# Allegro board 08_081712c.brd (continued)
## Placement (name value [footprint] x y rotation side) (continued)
R474  33  [R0603]  205.49 25.97 90 top
R475  1K  [R0402]  205.61 15.81 90 top
R476  10  [R0402]  198.63 17.97 180 top
R477  150  [R0402]  190.75 18.86 0 top
R478  10  [R0402]  198.63 19.75 180 top
R479  5.1K  [R0402]  206.12 12.13 180 top
R480  5.1K  [R0402]  210.69 10.86 180 bottom
R481  30.1K  [R0201]  205.49 10.86 180 bottom
R482  47K  [R0201]  203.71 10.86 180 bottom
R483  18.2K  [R0402]  224.03 14.16 0 top
R484  10K  [R0201]  190.88 29.53 90 top
R485  10K  [R0201]  196.21 30.04 90 top
R486  100K  [R0402]  218.19 12.26 0 top
R487  330  [R0402]  197.61 30.42 90 top
R488  1K  [R0402]  195.71 62.8 270 top
R489  3K  [R0402]  213.49 48.83 270 top
R490  49.9K  [R0402]  198.25 48.83 90 top
R491  100K  [R0402]  197.1 48.83 270 top
R492  33  [R0603]  212.85 38.42 90 top
R493  33  [R0603]  215.9 38.42 90 top
R494  33  [R0603]  214.38 38.42 90 top
R495  33  [R0603]  217.42 38.42 90 top
R496  10K  [R0201]  211.45 37.78 90 top
R497  0  [R0201]  229.49 19.75 270 top
R498  0  [R0201]  229.49 23.56 90 top
R499  33  [R0603]  191.77 33.85 90 bottom
R500  33  [R0603]  190.25 33.85 90 bottom
R501  33  [R0603]  193.29 33.85 90 bottom
R502  33  [R0402]  180.96 127.13 270 top
R503  33  [R0402]  179.69 127.13 270 top
R504  20K  [R0402]  25.27 115.51 180 bottom
R505  20K  [R0402]  25.27 114.36 180 bottom
R506  20K  [R0402]  25.27 113.22 180 bottom
R507  20K  [R0402]  25.27 112.08 180 bottom
R508  20K  [R0402]  25.27 110.93 180 bottom
R509  10K  [R0402]  25.27 115.51 180 top
R510  10K  [R0402]  25.27 114.36 180 top
R511  10K  [R0402]  25.27 113.22 180 top
R512  10K  [R0402]  25.27 112.08 180 top
R513  10K  [R0402]  25.27 110.93 180 top
R514  10K  [R0402]  70.74 81.28 90 top
R515  0  [R0402]  71.88 81.28 270 top
R516  2.94K  [R0402]  64.39 91.06 90 top
R517  10K  [R0402]  386.08 81.28 90 top
R518  0  [R0402]  387.22 81.28 270 top
R519  2.94K  [R0402]  379.73 91.06 90 top
R520  0  [R0402]  130.05 89.6 0 bottom
R521  0  [R0402]  130.05 91.12 0 bottom
R522  10K  [R0402]  240.28 90.04 0 top
R523  10K  [R0402]  203.2 71.95 0 top
R524  10K  [R0402]  137.41 88.58 0 bottom
R525  10K  [R0402]  264.41 88.58 0 bottom
R526  0  [R0402]  257.05 89.6 180 bottom
R527  0  [R0402]  257.05 91.12 180 bottom
R528  10K  [R0402]  203.2 70.8 180 top
R529  3K  [R0402]  279.65 78.55 90 bottom
R530  3K  [R0402]  277.62 78.55 90 bottom
R531  0  [R0402]  207.26 70.8 0 top
R532  0  [R0402]  202.18 63.69 0 top
R533  10K  [R0402]  10.41 32.64 180 bottom
R534  10K  [R0402]  378.08 32.64 180 bottom
R535  10K  [R0402]  86.23 39.5 0 top
R536  10K  [R0402]  88.77 39.5 0 top
R537  10K  [R0402]  88.77 37.97 180 top
R538  10K  [R0402]  86.23 37.97 180 top
R539  10K  [R0402]  72.14 39.5 0 top
R540  10K  [R0402]  74.68 39.5 0 top
R541  10K  [R0402]  74.68 37.97 180 top
R542  10K  [R0402]  72.14 37.97 180 top
R543  10K  [R0402]  349.15 39.47 0 top
R544  10K  [R0402]  351.69 39.47 0 top
R545  10K  [R0402]  351.69 37.95 180 top
R546  10K  [R0201]  243.71 27.05 0 bottom
R547  10K  [R0201]  246.51 24.89 180 bottom
R548  10K  [R0201]  241.05 24.24 0 bottom
R549  0  [R0402]  238.73 28.37 180 top
R550  0  [R0402]  233.15 28.75 180 top
R551  10K  [R0201]  233.15 26.47 0 top
R552  330  [R0402]  225.73 28.45 0 top
R553  10K  [R0402]  349.15 37.95 180 top
R554  10K  [R0402]  335.05 39.47 0 top
R555  10K  [R0402]  337.59 39.47 0 top
R556  10K  [R0402]  337.59 37.95 180 top
R557  10K  [R0402]  335.05 37.95 180 top
R558  3K  [R0402]  277.29 73.09 90 bottom
R559  3K  [R0402]  278.43 73.09 90 bottom
R560  3K  [R0402]  279.58 73.09 90 bottom
R561  3K  [R0402]  280.72 73.09 90 bottom
R562  3K  [R0402]  281.86 73.09 90 bottom
R563  3K  [R0402]  283.01 73.09 90 bottom
R564  10K  [R0603]  39.12 20.37 0 top
R565  75  [R0603]  36.07 20.37 0 top
R566  249  [R0805]  27.3 17.25 270 top
R567  107  [R0402]  26.8 14.91 180 top
R568  15K  [R0603]  400.69 20.37 0 top
R569  10K  [R0603]  406.78 20.37 0 top
R570  75  [R0603]  403.73 20.37 0 top
R571  249  [R0805]  394.97 17.25 270 top
R572  107  [R0402]  394.46 14.91 180 top
R573  33  [R0402]  19.18 26.29 0 top
R574  33  [R0402]  19.18 28.19 0 top
R575  33  [R0402]  9.27 28.96 180 top
R576  33  [R0402]  9.27 26.92 180 top
R577  33  [R0402]  97.92 114.05 90 top
R578  33  [R0402]  386.84 26.29 0 top
R579  33  [R0402]  386.84 28.19 0 top
R580  33  [R0402]  376.94 28.96 180 top
R581  33  [R0402]  376.94 26.92 180 top
R582  33  [R0402]  228.6 108.46 90 top
R583  0  [R0402]  205.77 74.36 270 top
R584  0  [R0402]  204.63 74.36 270 top
R585  0  [R0402]  210.34 82.74 0 top
R586  0  [R0402]  182.37 76.52 90 top
R587  0  [R0402]  309.4 76.52 90 top
R588  3K  [R0402]  152.65 78.55 90 bottom
R589  3K  [R0402]  150.62 78.55 90 bottom
R590  10K  [R0402]  151.26 92.01 180 top
R591  18.2K  [R0402]  105.41 56.77 180 bottom
R592  100K  [R0402]  96.9 58.8 180 bottom
R593  187K  [R0402]  100.84 56.77 0 bottom
R594  1MEG  [R0402_A]  96.39 56.77 90 bottom
R595  18.2K  [R0402]  232.41 56.77 180 bottom
R596  100K  [R0402]  223.9 58.8 180 bottom
R597  187K  [R0402]  227.84 56.77 0 bottom
R598  1MEG  [R0402_A]  223.39 56.77 90 bottom
R599  0  [R0402]  208.53 24.07 90 bottom
R600  60.4  [R0402]  188.85 77.72 90 bottom
R601  60.4  [R0402]  189.99 77.72 90 bottom
R602  60.4  [R0402]  191.13 77.72 90 bottom
R603  60.4  [R0402]  192.28 77.72 90 bottom
S1  JS102011JCQN  [SWSML335W142H220]  221.93 87.06 270 top
S2  JS102011JCQN  [SWSML335W142H220]  228.92 87.19 270 top
S3  JS102011JCQN  [SWSML335W142H220]  330.33 155.19 270 top
S4  JS102011JCQN  [SWSML335W142H220]  311.28 155.19 270 top
S5  JS102011JCQN  [SWSML335W142H220]  290.7 155.19 270 top
S6  JS102011JCQN  [SWSML335W142H220]  271.65 155.19 270 top
S7  JS102011JCQN  [SWSML335W142H220]  252.6 155.19 270 top
S8  JS102011JCQN  [SWSML335W142H220]  233.55 155.19 270 top
S9  JS102011JCQN  [SWSML335W142H220]  212.98 155.19 270 top
S10  JS102011JCQN  [SWSML335W142H220]  193.93 155.19 270 top
S11  MCDM(R)-08-T  [SWSML837W244H153]  204.6 55.82 180 top
S12  SD08H0SBR  [SWSML858W263H160]  72.64 58.17 180 top
S13  SD08H0SBR  [SWSML858W263H160]  330.2 58.17 180 top
S14  ELUMOASAQ6C12  [SWSML1110W450H237]  244.22 10.67 90 bottom
S15  KJ01RTR  [SWSML106W240H140]  146.68 90.23 90 top
S16  SD08H0SBR  [SWSML858W263H160]  170.81 131.45 90 top
SOMA  10151114-001TLF  [CNAMP10151114-001_MXM]  144.14 69.99 0 top
SOMB  10151114-001TLF  [CNAMP10151114-001_MXM]  271.15 69.99 0 top
TP1  TESTPAD  [TPSMC30]  103.39 92.14 270 top
TP2  TESTPAD  [TPSMC30]  99.94 92.14 270 top
TP3  TESTPAD  [TPSMC30]  97.4 83.31 270 top
TP4  TESTPAD  [TPSMC30]  101.09 91.02 270 top
TP5  TESTPAD  [TPSMC30]  97.4 87.88 270 top
TP6  TESTPAD  [TPSMC30]  104.9 79.2 270 top
TP7  TESTPAD  [TPSMC30]  111.38 87.46 270 top
TP8  TESTPAD  [TPSMC30]  102.93 79.98 270 top
TP9  TESTPAD  [TPSMC30]  108.39 90.25 270 top
TP10  TESTPAD  [TPSMC30]  112.53 86.32 270 top
TP11  TESTPAD  [TPSMC30]  107.04 79.98 270 top
TP12  TESTPAD  [TPSMC30]  106.43 91.02 270 top
TP13  TESTPAD  [TPSMC30]  111.38 85.18 270 top
TP14  WHT  [CNLOOPTP]  217.04 67.63 270 top
TP15  WHT  [CNLOOPTP]  221.61 67.63 270 top
TP16  TESTPAD  [TPC65D45]  387.1 114.68 0 top
TP17  TESTPAD  [TPC65D45]  387.1 160.27 0 top
TP18  TESTPAD  [TPC65D45]  406.91 109.73 180 top
TP19  TESTPAD  [TPC65D45]  406.91 155.32 180 top
TP20  TESTPAD  [TPC65D45]  387.1 137.54 0 top
TP21  TESTPAD  [TPC65D45]  387.1 180.72 0 top
TP22  TESTPAD  [TPC65D45]  406.91 132.59 180 top
TP23  BLK  [CNKEY5001TP]  216.92 6.29 0 top
TP24  BLK  [CNKEY5001TP]  226.06 6.29 0 top
TP25  5016  [CNKEY5016TP]  345.57 181.99 180 top
TP26  5016  [CNKEY5016TP]  400.37 180.34 90 top
TP27  5016  [CNKEY5016TP]  400.37 137.16 90 top
TP28  5016  [CNKEY5016TP]  400.37 114.3 90 top
TP29  5016  [CNKEY5016TP]  400.37 159.89 90 top
TP30  TESTPAD  [TPC65D45]  102.36 76.33 180 top
TP31  TESTPAD  [TPC65D45]  229.36 76.33 180 top
U1  ADIN1300CCPZ  [QFN40_6X6_PAD2_8X2_8_A]  136.52 43.44 270 bottom
U2  ADIN1300CCPZ  [QFN40_6X6_PAD2_8X2_8_A]  263.53 43.44 270 bottom
U3  LT8609EMSE#TRPBF  [MSOP10_PAD1_88X1_68]  399.42 130.81 270 top
U4  LT8609EMSE#TRPBF  [MSOP10_PAD1_88X1_68]  399.42 173.99 270 top
U5  SN74LVC2G14DBVR  [SOT23_6]  163.45 27.69 180 bottom
U6  SN74LVC2G14DBVR  [SOT23_6]  290.45 27.69 180 bottom
U7  TC7MBL3126CFT(EL)  [TSSOP14]  219.96 43.81 0 bottom
U8  ADP5587ACPZ-1  [QFN24_4X4_PAD2_1X2_1]  30.48 114.24 180 top
U9  TC7MBL3125CFT(EL)  [TSSOP14]  207.01 87.38 0 top
U10  24AA01T-I/OT  [SOT23-5L]  278.64 81.98 180 bottom
U11  NC7SP14L6X  [UPAK6]  124.27 41.21 180 bottom
U12  NC7SP14L6X  [UPAK6]  251.27 41.21 180 bottom
U13  ADP223ACPZ  [QFN8_2X2_PAD1_6X1]  219.07 78.74 0 bottom
U14  TC7MBL3257CFK(EL)  [VSSOP16]  236.6 96.27 270 top
U15  TC7MBL3257CFK(EL)  [VSSOP16]  236.6 81.66 270 top
U16  LSF0204GU12-Q100X  [UQFN12_2X1_7]  307.85 111.38 0 top
U17  LSF0204GU12-Q100X  [UQFN12_2X1_7]  230.12 111.38 0 top
U18  ADAU1979WBCPZ  [QFN40_6X6_PAD3_9X3_9]  300.99 121.67 270 top
U19  ADAU1979WBCPZ  [QFN40_6X6_PAD3_9X3_9]  223.27 121.67 270 top
U20  LSF0204GU12-Q100X  [UQFN12_2X1_7]  301.5 111.38 0 top
U21  LSF0204GU12-Q100X  [UQFN12_2X1_7]  223.77 111.38 0 top
U22  ADA4841-2YRZ  [SO8]  330.33 147.57 90 top
U23  ADA4841-2YRZ  [SO8]  311.28 147.57 90 top
U24  ADA4841-2YRZ  [SO8]  290.7 147.57 90 top
U25  ADA4841-2YRZ  [SO8]  271.65 147.57 90 top
U26  ADA4841-2YRZ  [SO8]  252.6 147.57 90 top
U27  ADA4841-2YRZ  [SO8]  233.55 147.57 90 top
U28  ADA4841-2YRZ  [SO8]  212.98 147.57 90 top
U29  ADA4841-2YRZ  [SO8]  193.93 147.57 90 top
U30  NXU0104GU12-Q100X  [QFN12_2X1_7]  115.06 103.87 0 top
U31  NXU0104GU12-Q100X  [QFN12_2X1_7]  118.49 103.87 180 bottom
U32  LSF0204GU12-Q100X  [UQFN12_2X1_7]  126.24 103.87 0 top
U33  ADAU1966AWBSTZ  [LQFP80]  108.08 121.67 270 top
U34  TC7MBL3257CFK(EL)  [VSSOP16]  299 102.6 270 bottom
U35  TC7MBL3257CFK(EL)  [VSSOP16]  309.04 102.6 270 bottom
U36  TC7MBL3257CFK(EL)  [VSSOP16]  221.28 102.6 270 bottom
U37  TC7MBL3257CFK(EL)  [VSSOP16]  231.31 102.6 270 bottom
U38  TC7MBL3257CFK(EL)  [VSSOP16]  112.86 96.91 90 bottom
U39  TC7MBL3257CFK(EL)  [VSSOP16]  130.38 96.91 90 bottom
U40  TC7MBL3257CFK(EL)  [VSSOP16]  122.09 96.89 270 bottom
U41  ADM3056EBRIZ  [SO16WB_A]  88.65 31.12 180 top
U42  ADM3056EBRIZ  [SO16WB_A]  74.55 31.12 180 top
U43  ADM3056EBRIZ  [SO16WB_A]  351.56 31.09 180 top
U44  ADM3056EBRIZ  [SO16WB_A]  337.46 31.09 180 top
U45  TC7MBL3257CFK(EL)  [VSSOP16]  125.35 81.72 90 bottom
U46  TC7MBL3257CFK(EL)  [VSSOP16]  141.86 81.72 90 bottom
U47  TC7MBL3257CFK(EL)  [VSSOP16]  252.35 81.72 90 bottom
U48  TC7MBL3257CFK(EL)  [VSSOP16]  268.86 81.72 90 bottom
U49  LT8609EMSE#TRPBF  [MSOP10_PAD1_88X1_68]  399.42 153.54 270 top
U50  LT8609EMSE#TRPBF  [MSOP10_PAD1_88X1_68]  399.42 107.95 270 top
U51  ADP5587ACPZ-1  [QFN24_4X4_PAD2_1X2_1]  258.44 119.32 180 top
U52  TC7MBL3257CFK(EL)  [VSSOP16]  236.6 88.77 270 top
U53  IS25LP032D-JKLE  [WSON8_5X6_PAD4X3_4]  202.44 34.99 270 top
U54  ATSAME70Q21B-CFNT  [BGA144_6X6]  206.65 20.51 90 top
U55  LT8618EDDB-3.3#TRPBF  [DFN10_3X2_PAD2_39X0_64]  221.23 12.26 90 top
U56  ADM6315-29D2ARTZR7  [SOT143A]  193.55 29.4 90 top
U57  ADP151ACBZ-1.8-R7  [WLCSP4H26]  232.03 20.64 0 top
U58  74AVC4T245BQ,115  [DQFN16_3_5X2_5_PAD2_15X1_15]  214.63 34.35 0 top
U59  74AVC2T245GUX  [QFN10_1_8X1_4]  219.96 21.91 0 top
U60  74AVC4T245BQ,115  [DQFN16_3_5X2_5_PAD2_15X1_15]  192.02 37.78 180 bottom
U61  TC7MBL3257CFK(EL)  [VSSOP16]  133.73 89.85 90 bottom
U62  TC7MBL3257CFK(EL)  [VSSOP16]  260.73 89.85 90 bottom
U63  LSF0204GU12-Q100X  [UQFN12_2X1_7]  14.35 22.35 180 top
U64  74LVC1G08GW-Q100  [SOT353]  243.71 24.89 270 bottom
U65  IS72WVO32M8AWO256-200HLA2  [BGA24_8X6]  104.39 85.09 0 bottom
U66  LTC2916HDDB-1#TRMPBF  [DFN8_3X2_PAD2_15X0_56_05-08-1702]  235.94 28.12 90 top
U67  TC7MBL3257CFK(EL)  [VSSOP16]  14.1 31.37 270 bottom
U68  LSF0204GU12-Q100X  [UQFN12_2X1_7]  382.02 22.35 180 top
U69  TC7MBL3257CFK(EL)  [VSSOP16]  381.76 31.37 270 bottom
U70  SN65LVDS2DR  [SO8NB-5]  37.34 25.2 0 top
U71  SN74LVC1G08DBVT  [SOT23-5L-2]  28.19 23.16 180 top
U72  SN65LVDS2DR  [SO8NB-5]  405 25.2 0 top
U73  SN74LVC1G08DBVT  [SOT23-5L-2]  395.86 23.16 180 top
U74  TC7MBL3125CFT(EL)  [TSSOP14]  14.22 26.92 180 top
U75  TC7MBL3125CFT(EL)  [TSSOP14]  381.89 26.92 180 top
U76  24AA01T-I/OT  [SOT23-5L]  151.64 81.98 180 bottom
U77  LT8609EMSE#TRPBF  [MSOP10_PAD1_88X1_68]  102.49 59.31 270 bottom
U78  LT8609EMSE#TRPBF  [MSOP10_PAD1_88X1_68]  229.49 59.31 270 bottom
U79  LSF0204GU12-Q100X  [UQFN12_2X1_7]  190.37 80.9 0 bottom
U80  LSF0204GU12-Q100X  [UQFN12_2X1_7]  190.37 86.36 0 top
U81  NXU0104GU12-Q100X  [QFN12_2X1_7]  180.12 123.22 180 top
Y1  25MEGHZ  [YSML79W63H32]  145.8 38.23 270 bottom
Y2  25MEGHZ  [YSML79W63H32]  272.8 38.23 270 bottom
Y3  24.576MEGHZ  [YSML98W79H35]  183.51 128.35 180 top
Y5  32.768KHZ  [YSML126W59H26]  208.88 26.86 180 top
Y6  12MEGHZ  [YSML126W98H31]  213.99 18.1 45 top

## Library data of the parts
A1 A2 = ADA4610_1_V2: User Part Number: UPN; Tolerance: N/A; alternate symbols: (SOT23-5L); tolerance: N/A
C1-C27 C32-C35 C37 C39-C53 C58-C61 C63 C65-C68 C72-C80 C85-C88 C91-C98 C101 C102 C105-C110 C168-C173 C175 C176 C178 C179 C181 C183 C192 C194-C198 C263-C293 C295 C297 C299 C311 C312 C330 C339 C341 C344 C351 C359 C361-C382 C385-C390 C393 C397 C398 C417 C423 C428-C433 = CAP: User Part Number: UPN; Tolerance: 10; alternate symbols: (C0402); tolerance: 10
C28 C29 C36 C54 C55 C62 = CAP: User Part Number: UPN; Tolerance: 10; alternate symbols: (C0805); tolerance: 10
C30 C31 C38 C56 C57 C64 C117-C120 C131-C134 C145-C148 C159-C162 C188 C190 C191 C193 = CAP: User Part Number: UPN; Tolerance: 10; alternate symbols: (C0603); tolerance: 10
C69-C71 = CAP: Tolerance: 10; User Part Number: UPN; alternate symbols: (C0805H60); tolerance: 10
C81 C82 C89 C90 C99 C100 = CAP: User Part Number: UPN; Tolerance: 10; alternate symbols: (C0805H55); tolerance: 10
C83 C84 C111 C112 C125 C126 C139 C140 C153 C154 C174 C303 C304 C315 C316 C321-C324 C326-C329 C331-C338 C340 C342 C345 C346 C348-C350 C352-C354 C357 C358 C383 C394 C396 C419 C425 = CAP: User Part Number: UPN; Tolerance: 5; alternate symbols: (C0402); tolerance: 5
C103 C104 = CAP: Tolerance: 20; User Part Number: UPN; alternate symbols: (C1210H110); tolerance: 20
C113-C116 C121-C124 C127-C130 C135-C138 C141-C144 C149-C152 C155-C158 C163-C166 = CAPP: Tolerance: 20; User Part Number: UPN; alternate symbols: (CPLSMSQ169H217); tolerance: 20
C167 C177 C180 C182 C184-C187 C189 C294 C296 C309 C310 C384 C391 C392 C416 C422 = CAP: Tolerance: 10; User Part Number: UPN; alternate symbols: (C0805H53); tolerance: 10
C199-C206 C215-C222 C231-C238 C247-C250 C255-C258 C399-C414 = CAP: User Part Number: UPN; Tolerance: 5; alternate symbols: (C0805); tolerance: 5
C207-C214 C223-C230 C239-C246 C251-C254 C259-C262 = CAPP: Tolerance: 10; User Part Number: UPN; alternate symbols: (C2312); tolerance: 10
C298 = CAP: User Part Number: UPN; Tolerance: 5; alternate symbols: (C1206); tolerance: 5
C300 C301 C313 C314 C418 C424 = CAP: Tolerance: 5; User Part Number: UPN; alternate symbols: (C0805-2); tolerance: 5
C302 C415 = CAP: Tolerance: -20%, +80%; User Part Number: UPN; alternate symbols: (C1210); tolerance: -20%, +80%
C305 C306 C317 C318 C420 C426 = CAP: Tolerance: 10; User Part Number: UPN; alternate symbols: (C1210H106); tolerance: 10
C307 C308 C319 C320 C421 C427 = CAP: Tolerance: -20%, +80%; User Part Number: UPN; alternate symbols: (C1206H71-2); tolerance: -20%, +80%
C325 C347 = CAP: Tolerance: 10; User Part Number: UPN; alternate symbols: (C0201); tolerance: 10
C343 C355 C356 = CAP: User Part Number: UPN; Tolerance: 20; alternate symbols: (C0603); tolerance: 20
C360 C395 = CAP: User Part Number: UPN; Tolerance: 20; alternate symbols: (C0402); tolerance: 20
D1-D4 = DIOTVS6P_V2: User Part Number: UPN; Tolerance: N/A; alternate symbols: (SOT23_6); tolerance: N/A
D5-D8 = DIO3P_V5: User Part Number: UPN; Tolerance: N/A; alternate symbols: (SOT23-M3); tolerance: N/A
D9 D10 = DIOSCHOTTKY: User Part Number: UPN; Tolerance: N/A; alternate symbols: (SMC); tolerance: N/A
D11 = DIOZNR: User Part Number: UPN; Tolerance: 5; alternate symbols: (SOD123-2); tolerance: 5
D12 = DIOLED_4P_V32: User Part Number: UPN; Tolerance: N/A; alternate symbols: (LED1210H28); tolerance: N/A
D13 = DIOTVS5P_V4: User Part Number: UPN; Tolerance: N/A; alternate symbols: (SC70-5_A); tolerance: N/A
DS1-DS20 DS24-DS26 = DIOLED: Tolerance: N/A; User Part Number: UPN; alternate symbols: (LED0603); tolerance: N/A
DS21 DS22 = DIOLED: User Part Number: UPN; Tolerance: N/A; alternate symbols: (LED0603H50); tolerance: N/A
DS23 = DIOLED: Tolerance: N/A; User Part Number: UPN; alternate symbols: (LED0805_A); tolerance: N/A
E3-E5 = FERRITE: User Part Number: UPN; Tolerance: 25; alternate symbols: (L0402); tolerance: 25
F1 = FSFUSE: Tolerance: N/A; User Part Number: UPN; alternate symbols: (F2920); tolerance: N/A
J1 J2 = CN3P_V15: User Part Number: UPN; Tolerance: N/A; alternate symbols: (CNSWITCHCRAFTPJRAS1X2SXXXX); tolerance: N/A
J4 J5 P3 P4 = CN100P_V2: Tolerance: N/A; User Part Number: UPN; alternate symbols: (CNSAMTECLSS-150-01-X-DV-A); tolerance: N/A
L1 L5-L7 L9 L10 = IND: Tolerance: 20; User Part Number: UPN; alternate symbols: (LSML208W216H122); tolerance: 20
L2 = IND: User Part Number: UPN; Tolerance: 20; alternate symbols: (LSMSQ157H122); tolerance: 20
L3 L4 = IND: User Part Number: UPN; Tolerance: 5; alternate symbols: (L0402); tolerance: 5
L8 = IND: Tolerance: 20; User Part Number: UPN; alternate symbols: (LSMSQ118H47); tolerance: 20
M1 M2 = MODC6842135TR: User Part Number: UPN; Tolerance: N/A; alternate symbols: (MC6842135TR); tolerance: N/A
P1 P2 = CN20P_2PSHLD: Tolerance: N/A; User Part Number: UPN; alternate symbols: (CNWURTH7499511440); tolerance: N/A
P5 P6 = CN16P: User Part Number: UPN; Tolerance: N/A; alternate symbols: (CNTHMHDR2X8L800W200H343_OE); tolerance: N/A
P7 = CN3P: Tolerance: N/A; User Part Number: UPN; alternate symbols: (CNCUI-PJ-102A); tolerance: N/A
P8 = CN10P: User Part Number: UPN; Tolerance: N/A; alternate symbols: (CNTHMHDR2X5L500W200H215); tolerance: N/A
P9 = CN24PAB_2GND_6SHLD: Tolerance: N/A; User Part Number: UPN; alternate symbols: (CNWURTH632723300011); tolerance: N/A
P10 = CN3P: Tolerance: N/A; User Part Number: UPN; alternate symbols: (CNHDR1X3H391); tolerance: N/A
P11-P13 P15 = CN13P_4GND: User Part Number: UPN; Tolerance: N/A; alternate symbols: (CNKYCONSTX-4335-5BGP-S1); tolerance: N/A
P14 = CN50P_AB_4SHLD: User Part Number: UPN; Tolerance: N/A; alternate symbols: (CNNOR178-025-513R57X); tolerance: N/A
P16 = CN25P: Tolerance: N/A; User Part Number: UPN; alternate symbols: (CNAMP747461-1); tolerance: N/A
P17 = CN3P: Tolerance: N/A; User Part Number: UPN; alternate symbols: (CNHDR1X3H340); tolerance: N/A
P18 P19 = CN18P_V2: User Part Number: UPN; Tolerance: N/A; alternate symbols: (CNNORCOMP_178-009-513R491); tolerance: N/A
P20 P21 P39 P40 = CN20P: Tolerance: N/A; User Part Number: UPN; alternate symbols: (CNBERG1X20H340LD36); tolerance: N/A
P22-P27 = CN6P: User Part Number: UPN; Tolerance: N/A; alternate symbols: (CNHDR1X6H343); tolerance: N/A
P28 P29 = CN2P: User Part Number: UPN; Tolerance: N/A; alternate symbols: (CNHDR1X2H330); tolerance: N/A
P30 P31 = CN16P_ODD_EVEN: Tolerance: N/A; User Part Number: UPN; alternate symbols: (CNSMMHDR2X8L650W220H220); tolerance: N/A
P32 P33 P37 = CN12P: Tolerance: N/A; User Part Number: UPN; alternate symbols: (CNHDR2X6H420LD35); tolerance: N/A
P34 = CN10P_ODD_EVEN: User Part Number: UPN; Tolerance: N/A; alternate symbols: (CNHDR2X5H220); tolerance: N/A
P35 = CN20P_V2: User Part Number: UPN; Tolerance: N/A; alternate symbols: (CNTHMHDR2X10L750W220H215); tolerance: N/A
P36 = CN2P: User Part Number: UPN; Tolerance: N/A; alternate symbols: (CNBERG69157-102); tolerance: N/A
P38 P42 = CN4P: Tolerance: N/A; User Part Number: UPN; alternate symbols: (CNSM1X4H380); tolerance: N/A
PB1-PB4 S14 = SWSPDT_V14: User Part Number: UPN; Tolerance: N/A; alternate symbols: (SWSML1110W450H237); tolerance: N/A
Q1 = TRANFZT953: User Part Number: UPN; Tolerance: N/A; alternate symbols: (SOT223-2); tolerance: N/A
R1-R8 R13-R30 R40 R52-R55 R58-R62 R66 R67 R71 R72 R74-R81 R84-R87 R90-R94 R98 R99 R103 R104 R106-R113 R120 R123 R126-R134 R137-R150 R265 R268-R270 R272 R274-R279 R282-R284 R362 R363 R370 R371 R384-R387 R420-R437 R441 R442 R449-R452 R457-R459 R462 R486 R487 R489 R491 R502 R503 R509-R513 R523 R528-R530 R552 R558-R563 R577 R582 R588 R589 R592 R596 = RES: User Part Number: UPN; Tolerance: 5; alternate symbols: (R0402); tolerance: 5
R9-R12 R57 R89 R440 = RES: User Part Number: UPN; Tolerance: 0.1; alternate symbols: (R0402); tolerance: 0.1
R31-R36 R50 R51 R56 R63-R65 R68-R70 R73 R82 R83 R88 R95-R97 R100-R102 R105 R114 R115 R121 R122 R124 R125 R151-R156 R181-R184 R209-R212 R237-R240 R266 R271 R273 R280 R293-R300 R309-R316 R325-R332 R337-R340 R345-R355 R358-R361 R366-R369 R408-R411 R438 R439 R443 R444 R447 R448 R453 R454 R463 R468 R471 R472 R475-R480 R483 R488 R504-R508 R514 R516 R517 R519 R522 R524 R525 R533-R545 R553-R557 R567 R572-R576 R578-R581 R590 R591 R593 R595 R597 R600-R603 = RES: User Part Number: UPN; Tolerance: 1; alternate symbols: (R0402); tolerance: 1
R37-R39 R41-R49 R135 R136 R159 R162 R165 R168 R187 R190 R193 R196 R215 R218 R221 R224 R243 R246 R249 R252 R281 R356 R357 R364 R365 R372-R383 R388-R407 R412-R419 R515 R518 R520 R521 R526 R527 R531 R532 R549 R550 R583-R587 R599 = RES: User Part Number: UPN; Tolerance: JUMPER; alternate symbols: (R0402); tolerance: JUMPER
R116 R118 = RES: Tolerance: 0.1; User Part Number: UPN; alternate symbols: (R0603H18); tolerance: 0.1
R117 R119 = RES: User Part Number: UPN; Tolerance: 0.02; alternate symbols: (R0603); tolerance: 0.02
R157 R160 R163 R166 R169-R172 R185 R188 R191 R194 R197-R200 R213 R216 R219 R222 R225-R228 R241 R244 R247 R250 R253-R256 = RES: User Part Number: UPN; Tolerance: 0.1; alternate symbols: (R0805); tolerance: 0.1
R158 R161 R164 R167 R186 R189 R192 R195 R214 R217 R220 R223 R242 R245 R248 R251 R285-R292 R301-R308 R317-R324 R333-R336 R341-R344 R566 R571 = RES: User Part Number: UPN; Tolerance: 1; alternate symbols: (R0805); tolerance: 1
R173-R180 R201-R208 R229-R236 R257-R264 R267 R564 R565 R568-R570 = RES: User Part Number: UPN; Tolerance: 1; alternate symbols: (R0603); tolerance: 1
R445 R446 R455 R456 R594 R598 = RES: Tolerance: 5; User Part Number: UPN; alternate symbols: (R0402_A); tolerance: 5
R460 R461 R497 R498 = RES: Tolerance: JUMPER; User Part Number: UPN; alternate symbols: (R0201); tolerance: JUMPER
R464-R467 R469 R470 R473 R481 R482 R484 R485 R496 R546-R548 R551 = RES: Tolerance: 1; User Part Number: UPN; alternate symbols: (R0201); tolerance: 1
R474 R492-R495 R499-R501 = RES: User Part Number: UPN; Tolerance: 5; alternate symbols: (R0603); tolerance: 5
R490 = RES: User Part Number: UPN; Tolerance: 0.5; alternate symbols: (R0402); tolerance: 0.5
S1-S10 = SWSPDT: User Part Number: UPN; Tolerance: N/A; alternate symbols: (SWSML335W142H220); tolerance: N/A
S11 = SWSPST16P_V2: User Part Number: UPN; Tolerance: N/A; alternate symbols: (SWSML837W244H153); tolerance: N/A
S12 S13 S16 = SWITCH8: User Part Number: UPN; Tolerance: N/A; alternate symbols: (SWSML858W263H160); tolerance: N/A
S15 = SWSPST2PIN_V2: Tolerance: N/A; User Part Number: UPN; alternate symbols: (SWSML106W240H140); tolerance: N/A
SOMA SOMB = CN274P_E4P_2SHLD: Tolerance: N/A; User Part Number: UPN; alternate symbols: (CNAMP10151114-001_MXM); tolerance: N/A
TP1-TP13 = NCTESTPAD: Tolerance: N/A; User Part Number: UPN; alternate symbols: (TPSMC30); tolerance: N/A
TP14 TP15 = CNTP1P: User Part Number: UPN; Tolerance: N/A; alternate symbols: (CNLOOPTP); tolerance: N/A
TP16-TP22 TP30 TP31 = NCTESTPAD: Tolerance: N/A; User Part Number: UPN; alternate symbols: (TPC65D45); tolerance: N/A
TP23 TP24 = CNTP1P: Tolerance: N/A; User Part Number: UPN; alternate symbols: (CNKEY5001TP); tolerance: N/A
TP25-TP29 = CNTP1P: Tolerance: N/A; User Part Number: UPN; alternate symbols: (CNKEY5016TP); tolerance: N/A
U1 U2 = ADIN1300: User Part Number: UPN; Tolerance: N/A; alternate symbols: (QFN40_6X6_PAD2_8X2_8_A); tolerance: N/A
U3 U4 U49 U50 U77 U78 = ADLT8609: User Part Number: UPN; Tolerance: N/A; alternate symbols: (MSOP10_PAD1_88X1_68); tolerance: N/A
U5 U6 = SN74LVC2G14: User Part Number: UPN; Tolerance: N/A; alternate symbols: (SOT23_6); tolerance: N/A
U7 = ICTC7MBL3126: Tolerance: N/A; User Part Number: ***; alternate symbols: (TSSOP14); tolerance: N/A
U8 U51 = ADP5587: Tolerance: N/A; User Part Number: UPN; alternate symbols: (QFN24_4X4_PAD2_1X2_1); tolerance: N/A
U9 U74 U75 = ICTC7MBL3125: Tolerance: N/A; User Part Number: ***; alternate symbols: (TSSOP14); tolerance: N/A
U10 U76 = IC24XX01: User Part Number: UPN; Tolerance: N/A; alternate symbols: (SOT23-5L); tolerance: N/A
U11 U12 = CMOSNC7SP14: Tolerance: N/A; User Part Number: UPN; alternate symbols: (UPAK6); tolerance: N/A
U13 = ADP22X: User Part Number: UPN; Tolerance: N/A; alternate symbols: (QFN8_2X2_PAD1_6X1); tolerance: N/A
U14 U15 U34-U40 U45-U48 U52 U61 U62 U67 U69 = CMOSTC7MBL3257CFK: Tolerance: N/A; User Part Number: UPN; alternate symbols: (VSSOP16); tolerance: N/A
U16 U17 U20 U21 U32 U63 U68 U79 U80 = ICLSF0204_V4: User Part Number: UPN; Tolerance: N/A; alternate symbols: (UQFN12_2X1_7); tolerance: N/A
U18 U19 = ADAU1979: User Part Number: UPN; Tolerance: N/A; alternate symbols: (QFN40_6X6_PAD3_9X3_9); tolerance: N/A
U22-U29 = ADA4841_2: Tolerance: N/A; User Part Number: UPN; alternate symbols: (SO8); tolerance: N/A
U30 U31 U81 = ICNXU0104GU12: Tolerance: N/A; alternate symbols: (QFN12_2X1_7); tolerance: N/A
U33 = ADAU1966: Tolerance: N/A; User Part Number: UPN; alternate symbols: (LQFP80); tolerance: N/A
U41-U44 = ADM3056E: User Part Number: UPN; Tolerance: N/A; alternate symbols: (SO16WB_A); tolerance: N/A
U53 = ICIS25LPXXX_V2: User Part Number: UPN; Tolerance: N/A; alternate symbols: (WSON8_5X6_PAD4X3_4); tolerance: N/A
U54 = ICATSAMXXXQ21X_CFX: Tolerance: N/A; User Part Number: UPN; alternate symbols: (BGA144_6X6); tolerance: N/A
U55 = ADLT8618: User Part Number: UPN; Tolerance: N/A; alternate symbols: (DFN10_3X2_PAD2_39X0_64); tolerance: N/A
U56 = ADM6315: User Part Number: UPN; Tolerance: N/A; alternate symbols: (SOT143A); tolerance: N/A
U57 = ADP151_V2: Tolerance: N/A; User Part Number: UPN; alternate symbols: (WLCSP4H26); tolerance: N/A
U58 U60 = 74245_V6: Tolerance: N/A; User Part Number: UPN; alternate symbols: (DQFN16_3_5X2_5_PAD2_15X1_15); tolerance: N/A
U59 = 74245_V9: User Part Number: UPN; Tolerance: N/A; alternate symbols: (QFN10_1_8X1_4); tolerance: N/A
U64 = 7408_V6: User Part Number: UPN; Tolerance: N/A; alternate symbols: (SOT353); tolerance: N/A
U65 = ICIS7XWVOXXM8: Tolerance: N/A; User Part Number: UPN; alternate symbols: (BGA24_8X6); tolerance: N/A
U66 = ADLTC291X_V2: User Part Number: UPN; Tolerance: N/A; alternate symbols: (DFN8_3X2_PAD2_15X0_56_05-08-1702); tolerance: N/A
U70 U72 = ICSN65LVDS2_V2: Tolerance: N/A; User Part Number: UPN; alternate symbols: (SO8NB-5); tolerance: N/A
U71 U73 = 7408_V3: User Part Number: UPN; Tolerance: N/A; alternate symbols: (SOT23-5L-2); tolerance: N/A
Y1 Y2 = XTALOSC4P_V2: Tolerance: N/A; User Part Number: UPN; alternate symbols: (YSML79W63H32); tolerance: N/A
Y3 = XTALOSC4P_V18: Tolerance: 30PPM; User Part Number: UPN; alternate symbols: (YSML98W79H35); tolerance: 30PPM
Y5 = XTAL: User Part Number: UPN; Tolerance: 20PPM; alternate symbols: (YSML126W59H26); tolerance: 20PPM
Y6 = XTAL4PIN_V3: Tolerance: 20; User Part Number: UPN; alternate symbols: (YSML126W98H31); tolerance: 20

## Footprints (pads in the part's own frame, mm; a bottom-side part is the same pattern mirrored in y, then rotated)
BGA24_8X6
  round 0.305 smd: A2(-2,-1) A3(-2,0) A4(-2,1) A5(-2,2) B1(-1,-2) B2(-1,-1) B3(-1,0) B4(-1,1) B5(-1,2) C1(0,-2) C2(0,-1) C3(0,0) C4(0,1) C5(0,2) D1(1,-2) D2(1,-1) D3(1,0) D4(1,1) D5(1,2) E1(2,-2) E2(2,-1) E3(2,0) E4(2,1) E5(2,2)
BGA144_6X6
  round 0.203 smd: A1(-2.4,-2.4) A2(-2.4,-2) A3(-2.4,-1.6) A4(-2.4,-1.2) A5(-2.4,-0.8) A6(-2.4,-0.4) A7(-2.4,0) A8(-2.4,0.4) A9(-2.4,0.8) A10(-2.4,1.2) A11(-2.4,1.6) A12(-2.4,2) A13(-2.4,2.4) B1(-2,-2.4) B2(-2,-2) B3(-2,-1.6) B4(-2,-1.2) B5(-2,-0.8) B6(-2,-0.4) B7(-2,0) B8(-2,0.4) B9(-2,0.8) B10(-2,1.2) B11(-2,1.6) B12(-2,2) B13(-2,2.4) C1(-1.6,-2.4) C2(-1.6,-2) C3(-1.6,-1.6) C4(-1.6,-1.2) C5(-1.6,-0.8) C6(-1.6,-0.4) C7(-1.6,0) C8(-1.6,0.4) C9(-1.6,0.8) C10(-1.6,1.2) C11(-1.6,1.6) C12(-1.6,2) C13(-1.6,2.4) D1(-1.2,-2.4) D2(-1.2,-2) D3(-1.2,-1.6) D4(-1.2,-1.2) D5(-1.2,-0.8) D6(-1.2,-0.4) D7(-1.2,0) D8(-1.2,0.4) D9(-1.2,0.8) D10(-1.2,1.2) D11(-1.2,1.6) D12(-1.2,2) D13(-1.2,2.4) E1(-0.8,-2.4) E2(-0.8,-2) E3(-0.8,-1.6) E4(-0.8,-1.2) E10(-0.8,1.2) E11(-0.8,1.6) E12(-0.8,2) E13(-0.8,2.4) F1(-0.4,-2.4) F2(-0.4,-2) F3(-0.4,-1.6) F4(-0.4,-1.2) F10(-0.4,1.2) F11(-0.4,1.6) F12(-0.4,2) F13(-0.4,2.4) G1(0,-2.4) G2(0,-2) G3(0,-1.6) G4(0,-1.2) G10(0,1.2) G11(0,1.6) G12(0,2) G13(0,2.4) H1(0.4,-2.4) H2(0.4,-2) H3(0.4,-1.6) H4(0.4,-1.2) H10(0.4,1.2) H11(0.4,1.6) H12(0.4,2) H13(0.4,2.4) J1(0.8,-2.4) J2(0.8,-2) J3(0.8,-1.6) J4(0.8,-1.2) J10(0.8,1.2) J11(0.8,1.6) J12(0.8,2) J13(0.8,2.4) K1(1.2,-2.4) K2(1.2,-2) K3(1.2,-1.6) K4(1.2,-1.2) K5(1.2,-0.8) K6(1.2,-0.4) K7(1.2,0) K8(1.2,0.4) K9(1.2,0.8) K10(1.2,1.2) K11(1.2,1.6) K12(1.2,2) K13(1.2,2.4) L1(1.6,-2.4) L2(1.6,-2) L3(1.6,-1.6) L4(1.6,-1.2) L5(1.6,-0.8) L6(1.6,-0.4) L7(1.6,0) L8(1.6,0.4) L9(1.6,0.8) L10(1.6,1.2) L11(1.6,1.6) L12(1.6,2) L13(1.6,2.4) M1(2,-2.4) M2(2,-2) M3(2,-1.6) M4(2,-1.2) M5(2,-0.8) M6(2,-0.4) M7(2,0) M8(2,0.4) M9(2,0.8) M10(2,1.2) M11(2,1.6) M12(2,2) M13(2,2.4) N1(2.4,-2.4) N2(2.4,-2) N3(2.4,-1.6) N4(2.4,-1.2) N5(2.4,-0.8) N6(2.4,-0.4) N7(2.4,0) N8(2.4,0.4) N9(2.4,0.8) N10(2.4,1.2) N11(2.4,1.6) N12(2.4,2) N13(2.4,2.4)
C0201
  rect 0.305x0.406 smd: 1(-0.318,0) 2(0.318,0)
C0402
  rect 0.584x0.66 smd: 1(-0.5,0) 2(0.5,0)
C0603
  rect 0.94x0.991 smd: 1(-0.8,0) 2(0.8,0)
C0805
  rect 1.143x1.448 smd: 1(-0.9,0) 2(0.9,0)
C0805-2
  rect 0.991x1.245 smd: 1(-0.995,0) 2(0.995,0)
C0805H53
  rect 1.295x1.6 smd: 1(-0.953,0) 2(0.953,0)
C0805H55
  rect 1.143x1.448 smd: 1(-0.9,0) 2(0.9,0)
C0805H60
  rect 1.295x1.6 smd: 1(-0.953,0) 2(0.953,0)
C1206
  rect 1.143x1.803 smd: 1(-1.5,0) 2(1.5,0)
C1206H71-2
  rect 1.346x1.194 smd: 1(-1.423,0) 2(1.423,0)
C1210
  rect 1.575x2.692 smd: 1(-1.397,0) 2(1.397,0)
C1210H106
  rect 1.092x2.057 smd: 1(-1.646,0) 2(1.646,0)
C1210H110
  rect 1.372x2.794 smd: 1(-1.431,0) 2(1.431,0)
C2312
  rect 1.93x2.21 smd: N(2.54,0) P(-2.54,0)
CNAMP747461-1
  round 7.62 hole 3.175 unplated: (-6.96,9.652) (40.081,9.652)
  rect 1.397x1.397 hole 0.889: 1(0,0)
  round 1.397 hole 0.889: 2(2.76,0) 3(5.52,0) 4(8.28,0) 5(11.04,0) 6(13.8,0) 7(16.56,0) 8(19.32,0) 9(22.08,0) 10(24.84,0) 11(27.6,0) 12(30.36,0) 13(33.12,0) 14(1.38,2.845) 15(4.14,2.845) 16(6.9,2.845) 17(9.66,2.845) 18(12.42,2.845) 19(15.18,2.845) 20(17.94,2.845) 21(20.7,2.845) 22(23.46,2.845) 23(26.22,2.845) 24(28.98,2.845) 25(31.74,2.845)
CNAMP10151114-001_MXM
  round 2.362 hole 1.092 unplated: (-41,0)
  round 2.362 hole 1.6 unplated: (41,0)
  rect 0.356x2.007 smd: 1(-30,-3.75) 2(-29.75,3.5) 3(-29.5,-3.75) 4(-29.25,3.5) 5(-29,-3.75) 6(-28.75,3.5) 7(-28.5,-3.75) 8(-28.25,3.5) 9(-28,-3.75) 10(-27.75,3.5) 11(-27.5,-3.75) 12(-27.25,3.5) 13(-27,-3.75) 14(-26.75,3.5) 15(-26.5,-3.75) 16(-26.25,3.5) 17(-26,-3.75) 18(-25.75,3.5) 19(-25.5,-3.75) 20(-25.25,3.5) 21(-25,-3.75) 22(-24.75,3.5) 23(-24.5,-3.75) 24(-24.25,3.5) 25(-24,-3.75) 26(-23.75,3.5) 27(-23.5,-3.75) 28(-23.25,3.5) 29(-23,-3.75) 30(-22.75,3.5) 31(-22.5,-3.75) 32(-22.25,3.5) 33(-22,-3.75) 34(-21.75,3.5) 35(-21.5,-3.75) 36(-21.25,3.5) 37(-21,-3.75) 38(-20.75,3.5) 39(-20.5,-3.75) 40(-20.25,3.5) 41(-20,-3.75) 42(-19.75,3.5) 43(-19.5,-3.75) 44(-19.25,3.5) 45(-19,-3.75) 46(-18.75,3.5) 47(-18.5,-3.75) 48(-18.25,3.5) 49(-18,-3.75) 50(-17.75,3.5) 51(-17.5,-3.75) 52(-17.25,3.5) 53(-17,-3.75) 54(-16.75,3.5) 55(-16.5,-3.75) 56(-16.25,3.5) 57(-16,-3.75) 58(-15.75,3.5) 59(-15.5,-3.75) 60(-15.25,3.5) 61(-15,-3.75) 62(-14.75,3.5) 63(-14.5,-3.75) 64(-14.25,3.5) 65(-14,-3.75) 66(-13.75,3.5) 67(-13.5,-3.75) 68(-13.25,3.5) 69(-13,-3.75) 70(-12.75,3.5) 71(-12.5,-3.75) 72(-12.25,3.5) 73(-12,-3.75) 74(-11.75,3.5) 75(-11.5,-3.75) 76(-11.25,3.5) 77(-11,-3.75) 78(-10.75,3.5) 79(-10.5,-3.75) 80(-10.25,3.5) 81(-10,-3.75) 82(-9.75,3.5) 83(-9.5,-3.75) 84(-9.25,3.5) 85(-9,-3.75) 86(-8.75,3.5) 87(-8.5,-3.75) 88(-8.25,3.5) 89(-8,-3.75) 90(-7.75,3.5) 91(-7.5,-3.75) 92(-7.25,3.5) 93(-7,-3.75) 94(-6.75,3.5) 95(-6.5,-3.75) 96(-6.25,3.5) 97(-6,-3.75) 98(-5.75,3.5) 99(-5.5,-3.75) 100(-5.25,3.5) 101(-5,-3.75) 102(-4.75,3.5) 103(-4.5,-3.75) 104(-4.25,3.5) 105(-4,-3.75) 106(-3.75,3.5) 107(-3.5,-3.75) 108(-3.25,3.5) 109(-3,-3.75) 110(-2.75,3.5) 111(-2.5,-3.75) 112(-2.25,3.5) 113(-2,-3.75) 114(-1.75,3.5) 115(-1.5,-3.75) 116(-1.25,3.5) 117(-1,-3.75) 118(-0.75,3.5) 119(-0.5,-3.75) 120(-0.25,3.5) 121(0,-3.75) 122(0.25,3.5) 123(0.5,-3.75) 124(0.75,3.5) 125(1,-3.75) 133(3,-3.75) 134(3.25,3.5) 135(3.5,-3.75) 136(3.75,3.5) 137(4,-3.75) 138(4.25,3.5) 139(4.5,-3.75) 140(4.75,3.5) 141(5,-3.75) 142(5.25,3.5) 143(5.5,-3.75) 144(5.75,3.5) 145(6,-3.75) 146(6.25,3.5) 147(6.5,-3.75) 148(6.75,3.5) 149(7,-3.75) 150(7.25,3.5) 151(7.5,-3.75) 152(7.75,3.5) 153(8,-3.75) 154(8.25,3.5) 155(8.5,-3.75) 156(8.75,3.5) 157(9,-3.75) 158(9.25,3.5) 159(9.5,-3.75) 160(9.75,3.5) 161(10,-3.75) 162(10.25,3.5) 163(10.5,-3.75) 164(10.75,3.5) 165(11,-3.75) 166(11.25,3.5) 167(11.5,-3.75) 168(11.75,3.5) 169(12,-3.75) 170(12.25,3.5) 171(12.5,-3.75) 172(12.75,3.5) 173(13,-3.75) 174(13.25,3.5) 175(13.5,-3.75) 176(13.75,3.5) 177(14,-3.75) 178(14.25,3.5) 179(14.5,-3.75) 180(14.75,3.5) 181(15,-3.75) 182(15.25,3.5) 183(15.5,-3.75) 184(15.75,3.5) 185(16,-3.75) 186(16.25,3.5) 187(16.5,-3.75) 188(16.75,3.5) 189(17,-3.75) 190(17.25,3.5) 191(17.5,-3.75) 192(17.75,3.5) 193(18,-3.75) 194(18.25,3.5) 195(18.5,-3.75) 196(18.75,3.5) 197(19,-3.75) 198(19.25,3.5) 199(19.5,-3.75) 200(19.75,3.5) 201(20,-3.75) 202(20.25,3.5) 203(20.5,-3.75) 204(20.75,3.5) 205(21,-3.75) 206(21.25,3.5) 207(21.5,-3.75) 208(21.75,3.5) 209(22,-3.75) 210(22.25,3.5) 211(22.5,-3.75) 212(22.75,3.5) 213(23,-3.75) 214(23.25,3.5) 215(23.5,-3.75) 216(23.75,3.5) 217(24,-3.75) 218(24.25,3.5) 219(24.5,-3.75) 220(24.75,3.5) 221(25,-3.75) 222(25.25,3.5) 223(25.5,-3.75) 224(25.75,3.5) 225(26,-3.75) 226(26.25,3.5) 227(26.5,-3.75) 228(26.75,3.5) 229(27,-3.75) 230(27.25,3.5) 231(27.5,-3.75) 232(27.75,3.5) 233(28,-3.75) 234(28.25,3.5) 235(28.5,-3.75) 236(28.75,3.5) 237(29,-3.75) 238(29.25,3.5) 239(29.5,-3.75) 240(29.75,3.5) 241(30,-3.75) 242(30.25,3.5) 243(30.5,-3.75) 244(30.75,3.5) 245(31,-3.75) 246(31.25,3.5) 247(31.5,-3.75) 248(31.75,3.5) 249(32,-3.75) 250(32.25,3.5) 251(32.5,-3.75) 252(32.75,3.5) 253(33,-3.75) 254(33.25,3.5) 255(33.5,-3.75) 256(33.75,3.5) 257(34,-3.75) 258(34.25,3.5) 259(34.5,-3.75) 260(34.75,3.5) 261(35,-3.75) 262(35.25,3.5) 263(35.5,-3.75) 264(35.75,3.5) 265(36,-3.75) 266(36.25,3.5) 267(36.5,-3.75) 268(36.75,3.5) 269(37,-3.75) 270(37.25,3.5) 271(37.5,-3.75) 272(37.75,3.5) 273(38,-3.75) 274(38.25,3.5) 275(38.5,-3.75) 276(38.75,3.5) 277(39,-3.75) 278(39.25,3.5) 279(39.5,-3.75) 280(39.75,3.5) 281(40,-3.75)
  rect 4.826x2.007 smd: E1(-37.75,-3.75) E2(-37.5,3.5) E3(-32.75,-3.75) E4(-32.5,3.5)
  rect 2.997x5.156 smd: SH1(-44,0.75) SH2(44,0.75)
CNBERG1X20H340LD36
  rect 1.651x1.651 hole 1.143: 1(0,0)
  round 1.651 hole 1.143: 2(2.54,0) 3(5.08,0) 4(7.62,0) 5(10.16,0) 6(12.7,0) 7(15.24,0) 8(17.78,0) 9(20.32,0) 10(22.86,0) 11(25.4,0) 12(27.94,0) 13(30.48,0) 14(33.02,0) 15(35.56,0) 16(38.1,0) 17(40.64,0) 18(43.18,0) 19(45.72,0) 20(48.26,0)
CNBERG69157-102
  rect 1.524x1.524 hole 1.016: 1(0,0)
  round 1.524 hole 1.016: 2(2.54,0)
CNCUI-PJ-102A
  round 2.413 hole 1.905: 1(0,0) 2(6,0) 3(3,4.7)
CNHDR1X2H330
  rect 1.651x1.651 hole 1.143: 1(0,0)
  round 1.651 hole 1.143: 2(2.54,0)
CNHDR1X3H340
  rect 1.651x1.651 hole 1.143: 1(0,0)
  round 1.651 hole 1.143: 2(2.54,0) 3(5.08,0)
CNHDR1X3H391
  rect 1.27x2.21 smd: 1(-2.54,1.645) 2(0,-1.645) 3(2.54,1.645)
CNHDR1X6H343
  rect 1.651x1.651 hole 1.143: 1(0,0)
  round 1.651 hole 1.143: 2(2.54,0) 3(5.08,0) 4(7.62,0) 5(10.16,0) 6(12.7,0)
CNHDR2X5H220
  rect 0.737x2.794 smd: 1(-2.54,-2.032) 2(-2.54,2.032) 3(-1.27,-2.032) 4(-1.27,2.032) 5(0,-2.032) 6(0,2.032) 7(1.27,-2.032) 8(1.27,2.032) 9(2.54,-2.032) 10(2.54,2.032)
CNHDR2X6H420LD35
  rect 1.651x1.651 hole 1.143: 1(0,0)
  round 1.651 hole 1.143: 2(0,2.54) 3(2.54,0) 4(2.54,2.54) 5(5.08,0) 6(5.08,2.54) 7(7.62,0) 8(7.62,2.54) 9(10.16,0) 10(10.16,2.54) 11(12.7,0) 12(12.7,2.54)
CNKEY5001TP
  round 1.524 hole 1.016: 1(0,0)
CNKEY5016TP
  rect 4.699x3.429 smd: 1(0,0)
CNKYCONSTX-4335-5BGP-S1
  rect 1.524x1.524 hole 1.016: 1(0,0)
  round 1.524 hole 1.016: 2(-5,0) 3(-2.5,0) 4(2.5,0) 5(5,0) 22(-3.75,5) 23(-1.25,5) 24(1.25,5) 25(3.75,5) 32(-3.75,10) 33(-1.25,10) 34(1.25,10) 35(3.75,10)
  round 2.819 hole 2.311: GND1(-6.04,-3.8) GND2(6.04,-3.8) GND3(-6.04,7.5) GND4(6.04,7.5)
CNLOOPTP
  round 2.159 hole 1.6: 1(0,0)
CNNOR178-025-513R57X
  rect 1.778x1.778 hole 1.27: 1A(0,0) 1B(0,6.756)
  round 1.778 hole 1.27: 2A(-2.769,0) 2B(-2.769,6.756) 3A(-5.537,0) 3B(-5.537,6.756) 4A(-8.306,0) 4B(-8.306,6.756) 5A(-11.074,0) 5B(-11.074,6.756) 6A(-13.843,0) 6B(-13.843,6.756) 7A(-16.612,0) 7B(-16.612,6.756) 8A(-19.38,0) 8B(-19.38,6.756) 9A(-22.149,0) 9B(-22.149,6.756) 10A(-24.917,0) 10B(-24.917,6.756) 11A(-27.686,0) 11B(-27.686,6.756) 12A(-30.455,0) 12B(-30.455,6.756) 13A(-33.223,0) 13B(-33.223,6.756) 14A(-1.384,-2.845) 14B(-1.384,3.912) 15A(-4.153,-2.845) 15B(-4.153,3.912) 16A(-6.921,-2.845) 16B(-6.921,3.912) 17A(-9.69,-2.845) 17B(-9.69,3.912) 18A(-12.459,-2.845) 18B(-12.459,3.912) 19A(-15.227,-2.845) 19B(-15.227,3.912) 20A(-17.996,-2.845) 20B(-17.996,3.912) 21A(-20.765,-2.845) 21B(-20.765,3.912) 22A(-23.533,-2.845) 22B(-23.533,3.912) 23A(-26.302,-2.845) 23B(-26.302,3.912) 24A(-29.07,-2.845) 24B(-29.07,3.912) 25A(-31.839,-2.845) 25B(-31.839,3.912)
  round 3.556 hole 3.048: SH1(6.883,-2.845) SH2(6.883,5.155) SH3(-40.107,5.155) SH4(-40.107,-2.845)
CNNORCOMP_178-009-513R491
  round 4.318 hole 3.048 unplated: (-18.033,5.155) (-18.033,-2.845) (6.957,5.155) (6.957,-2.845)
  rect 1.778x1.778 hole 1.27: 1_1(0,0) 2_1(0,6.756)
  round 1.778 hole 1.27: 1_2(-2.769,0) 1_3(-5.537,0) 1_4(-8.306,0) 1_5(-11.074,0) 1_6(-1.384,-2.845) 1_7(-4.153,-2.845) 1_8(-6.921,-2.845) 1_9(-9.69,-2.845) 2_2(-2.769,6.756) 2_3(-5.537,6.756) 2_4(-8.306,6.756) 2_5(-11.074,6.756) 2_6(-1.384,3.912) 2_7(-4.153,3.912) 2_8(-6.921,3.912) 2_9(-9.69,3.912)
CNSAMTECLSS-150-01-X-DV-A
  round 1.016 hole 0.889 unplated: (-16.625,-1.1) (16.625,-1.1)
  rect 0.406x1.6 smd: 1(-15.557,1.8) 2(-15.557,-1.8) 3(-14.922,1.8) 4(-14.922,-1.8) 5(-14.287,1.8) 6(-14.287,-1.8) 7(-13.652,1.8) 8(-13.652,-1.8) 9(-13.018,1.8) 10(-13.018,-1.8) 11(-12.383,1.8) 12(-12.383,-1.8) 13(-11.748,1.8) 14(-11.748,-1.8) 15(-11.113,1.8) 16(-11.113,-1.8) 17(-10.477,1.8) 18(-10.477,-1.8) 19(-9.842,1.8) 20(-9.842,-1.8) 21(-9.207,1.8) 22(-9.207,-1.8) 23(-8.572,1.8) 24(-8.572,-1.8) 25(-7.938,1.8) 26(-7.938,-1.8) 27(-7.303,1.8) 28(-7.303,-1.8) 29(-6.668,1.8) 30(-6.668,-1.8) 31(-6.032,1.8) 32(-6.032,-1.8) 33(-5.397,1.8) 34(-5.397,-1.8) 35(-4.763,1.8) 36(-4.763,-1.8) 37(-4.128,1.8) 38(-4.128,-1.8) 39(-3.493,1.8) 40(-3.493,-1.8) 41(-2.857,1.8) 42(-2.857,-1.8) 43(-2.223,1.8) 44(-2.223,-1.8) 45(-1.587,1.8) 46(-1.587,-1.8) 47(-0.953,1.8) 48(-0.953,-1.8) 49(-0.318,1.8) 50(-0.318,-1.8) 51(0.318,1.8) 52(0.318,-1.8) 53(0.953,1.8) 54(0.953,-1.8) 55(1.587,1.8) 56(1.587,-1.8) 57(2.223,1.8) 58(2.223,-1.8) 59(2.857,1.8) 60(2.857,-1.8) 61(3.493,1.8) 62(3.493,-1.8) 63(4.128,1.8) 64(4.128,-1.8) 65(4.763,1.8) 66(4.763,-1.8) 67(5.397,1.8) 68(5.397,-1.8) 69(6.032,1.8) 70(6.032,-1.8) 71(6.668,1.8) 72(6.668,-1.8) 73(7.303,1.8) 74(7.303,-1.8) 75(7.938,1.8) 76(7.938,-1.8) 77(8.572,1.8) 78(8.572,-1.8) 79(9.207,1.8) 80(9.207,-1.8) 81(9.842,1.8) 82(9.842,-1.8) 83(10.477,1.8) 84(10.477,-1.8) 85(11.113,1.8) 86(11.113,-1.8) 87(11.748,1.8) 88(11.748,-1.8) 89(12.383,1.8) 90(12.383,-1.8) 91(13.018,1.8) 92(13.018,-1.8) 93(13.652,1.8) 94(13.652,-1.8) 95(14.287,1.8) 96(14.287,-1.8) 97(14.922,1.8) 98(14.922,-1.8) 99(15.557,1.8) 100(15.557,-1.8)
CNSM1X4H380
  rect 1.27x3.175 smd: 1(-3.81,1.587) 2(-1.27,-1.587) 3(1.27,1.587) 4(3.81,-1.587)
CNSMMHDR2X8L650W220H220
  rect 0.737x2.794 smd: 1(-4.445,-2.349) 2(-4.445,1.714) 3(-3.175,-2.349) 4(-3.175,1.714) 5(-1.905,-2.349) 6(-1.905,1.714) 7(-0.635,-2.349) 8(-0.635,1.714) 9(0.635,-2.349) 10(0.635,1.714) 11(1.905,-2.349) 12(1.905,1.714) 13(3.175,-2.349) 14(3.175,1.714) 15(4.445,-2.349) 16(4.445,1.714)
CNSWITCHCRAFTPJRAS1X2SXXXX
  oval 2.718x4.013 hole 1.702x2.997 unplated: (-2.4,-3.734) (9.893,-3.734)
  round 2.032 hole 1.524: S(7.493,-7.239)
  round 1.778 hole 1.27: T1(0,0) T2(7.493,0)
CNTHMHDR2X5L500W200H215
  rect 1.143x1.143 hole 0.737: 1(0,0)
  round 1.143 hole 0.737: 2(0,1.27) 3(1.27,0) 4(1.27,1.27) 5(2.54,0) 6(2.54,1.27) 7(3.81,0) 8(3.81,1.27) 9(5.08,0) 10(5.08,1.27)
CNTHMHDR2X8L800W200H343_OE
  rect 1.651x1.651 hole 1.143: 1(0,0)
  round 1.651 hole 1.143: 2(0,2.54) 3(2.54,0) 4(2.54,2.54) 5(5.08,0) 6(5.08,2.54) 7(7.62,0) 8(7.62,2.54) 9(10.16,0) 10(10.16,2.54) 11(12.7,0) 12(12.7,2.54) 13(15.24,0) 14(15.24,2.54) 15(17.78,0) 16(17.78,2.54)
CNTHMHDR2X10L750W220H215
  rect 1.143x1.143 hole 0.737: 1(0,0)
  round 1.143 hole 0.737: 2(0,1.27) 3(1.27,0) 4(1.27,1.27) 5(2.54,0) 6(2.54,1.27) 7(3.81,0) 8(3.81,1.27) 9(5.08,0) 10(5.08,1.27) 11(6.35,0) 12(6.35,1.27) 13(7.62,0) 14(7.62,1.27) 15(8.89,0) 16(8.89,1.27) 17(10.16,0) 18(10.16,1.27) 19(11.43,0) 20(11.43,1.27)
CNWURTH7499511440
  round 4.064 hole 2.794 unplated: (-11.425,-15.24) (1.275,-15.24)
  rect 1.397x1.397 hole 0.889: 1(0,0)
  round 1.397 hole 0.889: 2(-2.03,0) 3(-4.06,0) 4(-6.09,0) 5(-8.12,0) 6(-10.15,0) 7(1.015,2.54) 8(-1.015,2.54) 9(-3.045,2.54) 10(-7.105,2.54) 11(-9.135,2.54) 12(-11.165,2.54)
  round 1.143 hole 0.889: 13(0.515,-7.12) 14(-10.665,-7.12) 15(0.515,-8.58) 16(-10.665,-8.58)
  round 1.524 hole 1.016: 17(1.02,5.08) 18(-1.52,5.08) 19(-8.63,5.08) 20(-11.17,5.08)
  round 2.032 hole 1.524: SH1(2.99,-18.42) SH2(-13.14,-18.42)
CNWURTH632723300011
  rect 0.305x1.194 smd: A1(-2.75,4.577) A2(-2.25,4.577) A3(-1.75,4.577) A4(-1.25,4.577) A5(-0.75,4.577) A6(-0.25,4.577) A7(0.25,4.577) A8(0.75,4.577) A9(1.25,4.577) A10(1.75,4.577) A11(2.25,4.577) A12(2.75,4.577)
  round 0.66 hole 0.406: B1(2.8,3.33) B2(2.4,2.63) B3(1.6,2.63) B4(1.2,3.33) B5(0.8,2.63) B6(0.4,3.33) B7(-0.4,3.33) B8(-0.8,2.63) B9(-1.2,3.33) B10(-1.6,2.63) B11(-2.4,2.63) B12(-2.8,3.33) GND1(-2,3.33) GND2(2,3.33)
  oval 0.991x1.6 hole 0.61x1.219: SH1(-4.27,2.18) SH2(4.27,2.18) SH3(4.27,-2.55) SH4(-4.27,-2.55)
  rect 0.203x0.991 smd: SH5(0,-0.005) SH6(0,-3.105)
CPLSMSQ169H217
  rect 2.489x1.6 smd: N(1.745,0) P(-1.745,0)
DFN8_3X2_PAD2_15X0_56_05-08-1702
  oval 0.305x0.838 smd: 1(-0.75,-0.95) 2(-0.25,-0.95) 3(0.25,-0.95) 4(0.75,-0.95) 5(0.75,0.95) 6(0.25,0.95) 7(-0.25,0.95) 8(-0.75,0.95)
  rect 2.159x0.61 smd: 9(0,0)
DFN10_3X2_PAD2_39X0_64
  oval 0.305x0.838 smd: 1(-1,-0.95) 2(-0.5,-0.95) 3(0,-0.95) 4(0.5,-0.95) 5(1,-0.95) 6(1,0.95) 7(0.5,0.95) 8(0,0.95) 9(-0.5,0.95) 10(-1,0.95)
  rect 2.388x0.635 smd: PAD(0,0)
DQFN16_3_5X2_5_PAD2_15X1_15
  oval 0.889x0.229 smd: 1(-1.795,-0.25) 8(1.795,-0.25) 9(1.795,0.25) 16(-1.795,0.25)
  oval 0.229x0.889 smd: 2(-1.25,-1.294) 3(-0.75,-1.294) 4(-0.25,-1.294) 5(0.25,-1.294) 6(0.75,-1.294) 7(1.25,-1.294) 10(1.25,1.294) 11(0.75,1.294) 12(0.25,1.294) 13(-0.25,1.294) 14(-0.75,1.294) 15(-1.25,1.294)
  rect 1.905x0.991 smd: PAD(0,0)
F2920
  rect 2.286x3.048 smd: 1(-3.696,0) 2(3.696,0)
L0402
  rect 0.584x0.711 smd: 1(-0.475,0) 2(0.475,0)
LED0603
  rect 0.965x0.762 smd: A(0.8,0) C(-0.8,0)
LED0603H50
  rect 0.762x0.914 smd: A(0.801,0) C(-0.801,0)
LED0805_A
  rect 1.245x1.092 smd: A(1.172,0) C(-1.172,0)
LED1210H28
  rect 1.905x1.499 smd: 1(-1.602,0.924) 2(1.602,0.924) 3(-1.602,-0.924) 4(1.602,-0.924)
LQFP80
  rect 0.33x1.651 smd: 1(-6.175,-7.685) 2(-5.525,-7.685) 3(-4.875,-7.685) 4(-4.225,-7.685) 5(-3.575,-7.685) 6(-2.925,-7.685) 7(-2.275,-7.685) 8(-1.625,-7.685) 9(-0.975,-7.685) 10(-0.325,-7.685) 11(0.325,-7.685) 12(0.975,-7.685) 13(1.625,-7.685) 14(2.275,-7.685) 15(2.925,-7.685) 16(3.575,-7.685) 17(4.225,-7.685) 18(4.875,-7.685) 19(5.525,-7.685) 20(6.175,-7.685) 41(6.175,7.685) 42(5.525,7.685) 43(4.875,7.685) 44(4.225,7.685) 45(3.575,7.685) 46(2.925,7.685) 47(2.275,7.685) 48(1.625,7.685) 49(0.975,7.685) 50(0.325,7.685) 51(-0.325,7.685) 52(-0.975,7.685) 53(-1.625,7.685) 54(-2.275,7.685) 55(-2.925,7.685) 56(-3.575,7.685) 57(-4.225,7.685) 58(-4.875,7.685) 59(-5.525,7.685) 60(-6.175,7.685)
  rect 1.651x0.33 smd: 21(7.685,-6.175) 22(7.685,-5.525) 23(7.685,-4.875) 24(7.685,-4.225) 25(7.685,-3.575) 26(7.685,-2.925) 27(7.685,-2.275) 28(7.685,-1.625) 29(7.685,-0.975) 30(7.685,-0.325) 31(7.685,0.325) 32(7.685,0.975) 33(7.685,1.625) 34(7.685,2.275) 35(7.685,2.925) 36(7.685,3.575) 37(7.685,4.225) 38(7.685,4.875) 39(7.685,5.525) 40(7.685,6.175) 61(-7.685,6.175) 62(-7.685,5.525) 63(-7.685,4.875) 64(-7.685,4.225) 65(-7.685,3.575) 66(-7.685,2.925) 67(-7.685,2.275) 68(-7.685,1.625) 69(-7.685,0.975) 70(-7.685,0.325) 71(-7.685,-0.325) 72(-7.685,-0.975) 73(-7.685,-1.625) 74(-7.685,-2.275) 75(-7.685,-2.925) 76(-7.685,-3.575) 77(-7.685,-4.225) 78(-7.685,-4.875) 79(-7.685,-5.525) 80(-7.685,-6.175)
LSML208W216H122
  rect 1.168x4.394 smd: 1(-1.651,0) 2(1.651,0)
LSMSQ118H47
  rect 0.991x3.2 smd: 1(-0.995,0) 2(0.995,0)
LSMSQ157H122
  rect 0.965x3.708 smd: 1(-1.181,0) 2(1.181,0)
MC6842135TR
  round 2.997 hole 2.489 unplated: (-9.11,3.4) (-9.11,-3.54) (4.03,3.4) (4.03,-3.54)
  round 2.311 hole 2.108 unplated: (-5.09,3.4) (0.01,3.4)
  rect 1.524x1.524 hole 1.016: 1(0,0)
  round 1.524 hole 1.016: 2(-2.54,0) 3(-5.08,0) 4(0,-5) 5(-2.54,-5) 6(-5.08,-5)
MSOP10_PAD1_88X1_68
  rect 0.305x1.143 smd: 1(-1,-2.106) 2(-0.5,-2.106) 3(0,-2.106) 4(0.5,-2.106) 5(1,-2.106) 6(1,2.106) 7(0.5,2.106) 8(0,2.106) 9(-0.5,2.106) 10(-1,2.106)
  rect 1.88x1.676 smd: PAD(0,0)
QFN8_2X2_PAD1_6X1
  oval 0.305x0.864 smd: 1(-0.75,-1.13) 2(-0.25,-1.13) 3(0.25,-1.13) 4(0.75,-1.13) 5(0.75,1.13) 6(0.25,1.13) 7(-0.25,1.13) 8(-0.75,1.13)
  rect 1.6x0.991 smd: PAD(0,0)
QFN10_1_8X1_4
  oval 0.203x0.889 smd: 1(-0.2,-0.668)
  oval 0.203x0.813 smd: 2(0.2,-0.706) 6(0.2,0.706) 7(-0.2,0.706)
  oval 0.813x0.203 smd: 3(0.907,-0.4) 4(0.907,0) 5(0.907,0.4) 8(-0.907,0.4) 9(-0.907,0) 10(-0.907,-0.4)
QFN12_2X1_7
  rect 0.229x0.838 smd: 1(-0.8,-0.696) 2(-0.4,-0.696) 3(0,-0.696) 4(0.4,-0.696) 5(0.8,-0.696) 7(0.8,0.696) 8(0.4,0.696) 9(0,0.696) 10(-0.4,0.696) 11(-0.8,0.696)
  rect 0.838x0.229 smd: 6(0.846,0) 12(-0.846,0)
QFN24_4X4_PAD2_1X2_1
  oval 0.305x0.991 smd: 1(-1.25,-2) 2(-0.75,-2) 3(-0.25,-2) 4(0.25,-2) 5(0.75,-2) 6(1.25,-2) 13(1.25,2) 14(0.75,2) 15(0.25,2) 16(-0.25,2) 17(-0.75,2) 18(-1.25,2)
  oval 0.991x0.305 smd: 7(2,-1.25) 8(2,-0.75) 9(2,-0.25) 10(2,0.25) 11(2,0.75) 12(2,1.25) 19(-2,1.25) 20(-2,0.75) 21(-2,0.25) 22(-2,-0.25) 23(-2,-0.75) 24(-2,-1.25)
  rect 2.108x2.108 smd: PAD(0,0)
QFN40_6X6_PAD2_8X2_8_A
  oval 0.279x0.711 smd: 1(-2.25,-2.901) 2(-1.75,-2.901) 3(-1.25,-2.901) 4(-0.75,-2.901) 5(-0.25,-2.901) 6(0.25,-2.901) 7(0.75,-2.901) 8(1.25,-2.901) 9(1.75,-2.901) 10(2.25,-2.901) 21(2.25,2.901) 22(1.75,2.901) 23(1.25,2.901) 24(0.75,2.901) 25(0.25,2.901) 26(-0.25,2.901) 27(-0.75,2.901) 28(-1.25,2.901) 29(-1.75,2.901) 30(-2.25,2.901)
  oval 0.711x0.279 smd: 11(2.901,-2.25) 12(2.901,-1.75) 13(2.901,-1.25) 14(2.901,-0.75) 15(2.901,-0.25) 16(2.901,0.25) 17(2.901,0.75) 18(2.901,1.25) 19(2.901,1.75) 20(2.901,2.25) 31(-2.901,2.25) 32(-2.901,1.75) 33(-2.901,1.25) 34(-2.901,0.75) 35(-2.901,0.25) 36(-2.901,-0.25) 37(-2.901,-0.75) 38(-2.901,-1.25) 39(-2.901,-1.75) 40(-2.901,-2.25)
  rect 2.794x2.794 smd: PAD(0,0)
QFN40_6X6_PAD3_9X3_9
  oval 0.305x0.838 smd: 1(-2.25,-2.95) 2(-1.75,-2.95) 3(-1.25,-2.95) 4(-0.75,-2.95) 5(-0.25,-2.95) 6(0.25,-2.95) 7(0.75,-2.95) 8(1.25,-2.95) 9(1.75,-2.95) 10(2.25,-2.95) 21(2.25,2.95) 22(1.75,2.95) 23(1.25,2.95) 24(0.75,2.95) 25(0.25,2.95) 26(-0.25,2.95) 27(-0.75,2.95) 28(-1.25,2.95) 29(-1.75,2.95) 30(-2.25,2.95)
  oval 0.838x0.305 smd: 11(2.95,-2.25) 12(2.95,-1.75) 13(2.95,-1.25) 14(2.95,-0.75) 15(2.95,-0.25) 16(2.95,0.25) 17(2.95,0.75) 18(2.95,1.25) 19(2.95,1.75) 20(2.95,2.25) 31(-2.95,2.25) 32(-2.95,1.75) 33(-2.95,1.25) 34(-2.95,0.75) 35(-2.95,0.25) 36(-2.95,-0.25) 37(-2.95,-0.75) 38(-2.95,-1.25) 39(-2.95,-1.75) 40(-2.95,-2.25)
  rect 3.912x3.912 smd: PAD(0,0)
R0201
  rect 0.305x0.406 smd: 1(-0.318,0) 2(0.318,0)
R0402
  rect 0.635x0.737 smd: 1(-0.5,0) 2(0.5,0)
R0402_A
  rect 0.711x0.635 smd: 1(-0.635,0) 2(0.635,0)
R0603
  rect 0.787x0.991 smd: 1(-0.85,0) 2(0.85,0)
R0603H18
  rect 0.94x0.991 smd: 1(-0.787,0) 2(0.787,0)
R0805
  rect 1.041x1.397 smd: 1(-0.95,0) 2(0.95,0)
SC70-5_A
  rect 0.406x0.94 smd: 1(-0.65,-1.1) 2(0,-1.1) 3(0.65,-1.1) 4(0.65,1.1) 5(-0.65,1.1)
SMC
  rect 2.794x3.81 smd: A(3.569,0) C(-3.569,0)
SO8
  rect 0.61x2.184 smd: 1(-1.905,-2.54) 2(-0.635,-2.54) 3(0.635,-2.54) 4(1.905,-2.54) 5(1.905,2.54) 6(0.635,2.54) 7(-0.635,2.54) 8(-1.905,2.54)
SO8NB-5
  rect 0.635x1.829 smd: 1(-1.905,-2.591) 2(-0.635,-2.591) 3(0.635,-2.591) 4(1.905,-2.591) 5(1.905,2.591) 6(0.635,2.591) 7(-0.635,2.591) 8(-1.905,2.591)
SO16WB_A
  rect 0.61x2.007 smd: 1(-4.445,-4.65) 2(-3.175,-4.65) 3(-1.905,-4.65) 4(-0.635,-4.65) 5(0.635,-4.65) 6(1.905,-4.65) 7(3.175,-4.65) 8(4.445,-4.65) 9(4.445,4.65) 10(3.175,4.65) 11(1.905,4.65) 12(0.635,4.65) 13(-0.635,4.65) 14(-1.905,4.65) 15(-3.175,4.65) 16(-4.445,4.65)
SOD123-2
  rect 0.914x1.219 smd: A(1.638,0) C(-1.638,0)
SOT23-5L
  rect 0.508x1.524 smd: 1(-0.95,-1.17) 2(0,-1.17) 3(0.95,-1.17) 4(0.95,1.17) 5(-0.95,1.17)
SOT23-5L-2
  rect 0.61x1.194 smd: 1(-0.95,-1.15) 2(0,-1.15) 3(0.95,-1.15) 4(0.95,1.15) 5(-0.95,1.15)
SOT23-M3
  rect 0.787x0.889 smd: 1(-0.94,-1.003) 2(0.94,-1.003) 3(0,1.003)
SOT23_6
  rect 0.711x1.27 smd: 1(-0.953,-1.27) 2(0,-1.27) 3(0.953,-1.27) 4(0.953,1.27) 5(0,1.27) 6(-0.953,1.27)
SOT143A
  rect 1.092x1.27 smd: 1(-0.76,-1)
  rect 0.711x1.27 smd: 2(0.96,-1) 3(0.96,1) 4(-0.96,1)
SOT223-2
  rect 1.143x1.93 smd: 1(-2.286,-3.023) 2(0,-3.023) 3(2.286,-3.023)
  rect 2.997x1.93 smd: 4(0,3.023)
SOT353
  rect 0.33x0.94 smd: 1(-0.65,-0.89) 2(0,-0.89) 3(0.65,-0.89) 4(0.65,0.89) 5(-0.65,0.89)
